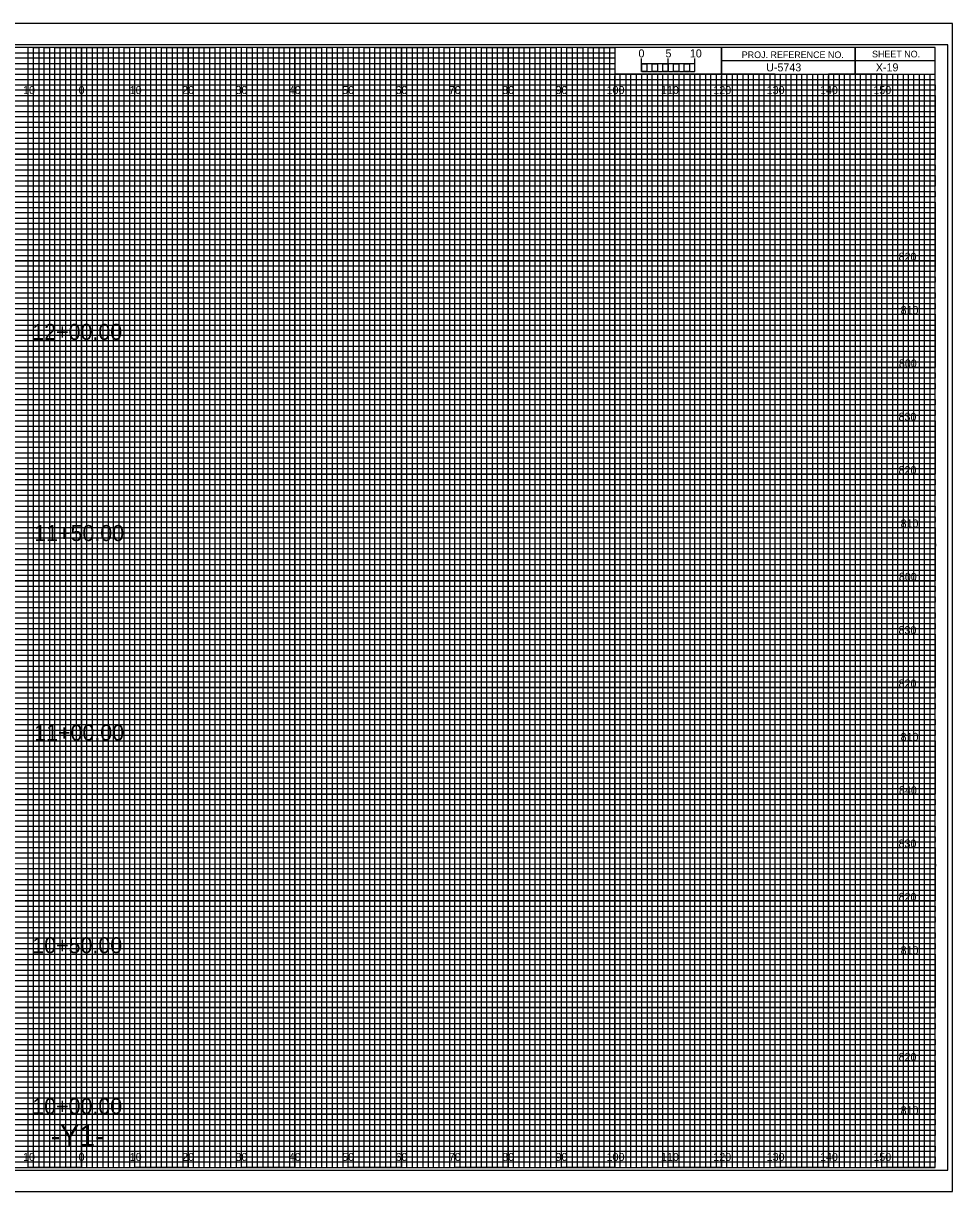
# Model space of a CAD drawing. Extents: x -13 to 323, y -4 to 214.
# Drawn here: x 149.1 to 323.3, y -4.5 to 214.5 of the extents above; entities that cross this region are included whole.
import ezdxf

# ---------------------------------------------------------------- set-up
doc = ezdxf.new("R2010")
doc.units = 0
for name, color, linetype in [('Exist Cross Section Cell', 7, 'Continuous'), ('Exist XS Center Line Elevation Label', 7, 'Continuous'), ('Exist XS Ground Line', 7, 'Continuous'), ('Old_Level_10', 7, 'Continuous'), ('Prop CMT Guardrail Graphics', 7, 'Continuous'), ('Prop CMT Pvmt Course 1', 7, 'Continuous'), ('Prop CMT Pvmt Course 2', 7, 'Continuous'), ('Prop CMT Pvmt Course 3', 7, 'Continuous'), ('Prop CMT Pvmt Surface', 7, 'Continuous'), ('Prop CMT Pvmt Surface Shoulder', 7, 'Continuous'), ('Prop CMT Shld Paved Course 1', 7, 'Continuous'), ('Prop CMT Shld Paved Course 2', 7, 'Continuous'), ('Prop CMT Shld Paved Course 3', 7, 'Continuous'), ('Prop CMT Slope Grass', 7, 'Continuous'), ('Prop CMT Subgrade Earthwork', 7, 'Continuous'), ('Prop XS Side Slope Text', 7, 'Continuous'), ('Scratch_Level_7', 7, 'Continuous')]:
    doc.layers.add(name, color=color, linetype=linetype)

msp = doc.modelspace()

# ---------------------------------------------------------------- linework, layer by layer
at = {"layer": 'Exist XS Center Line Elevation Label'}
for points in [[(145, 0), (155, 0), (155, 210), (165, 210), (165, 0), (175, 0), (175, 210), (185, 210), (185, 0), (195, 0), (195, 210), (205, 210), (205, 0), (215, 0), (215, 210), (225, 210), (225, 0), (235, 0), (235, 210), (245, 210), (245, 0), (255, 0), (255, 210), (259.93, 210), (260, 210), (260, 205), (264.99, 205), (264.99, 0), (275, 0), (275, 205), (285, 205), (285, 0), (295, 0), (295, 205), (305, 205), (305, 0), (315, 0), (315, 205)], [(0, 205), (275, 205)], [(0, 185), (320, 185), (320, 195), (0, 195)], [(0, 165), (320, 165), (320, 175), (0, 175)], [(0, 145), (320, 145), (320, 155), (0, 155)], [(0, 125), (320, 125), (320, 135), (0, 135)], [(0, 105), (320, 105), (320, 115), (0, 115)], [(0, 85), (320, 85), (320, 95), (0, 95)], [(0, 65), (320, 65), (320, 75), (0, 75)], [(0, 45), (320, 45), (320, 55), (0, 55)], [(0, 25), (320, 25), (320, 35), (0, 35)], [(0, 5), (320, 5), (320, 15), (0, 15)]]:
    msp.add_lwpolyline(points, dxfattribs=at)
at = {"layer": 'Exist XS Ground Line'}
for p, q in [((150, 210), (140, 210)), ((150, 0), (150, 210)), ((170, 210), (160, 210)), ((160, 210), (160, 0)), ((170, 0), (170, 210)), ((190, 210), (180, 210)), ((180, 210), (180, 0)), ((190, 0), (190, 210)), ((210, 210), (200, 210)), ((200, 210), (200, 0)), ((210, 0), (210, 210)), ((230, 210), (220, 210)), ((220, 210), (220, 0)), ((230, 0), (230, 210)), ((250, 210), (240, 210)), ((240, 210), (240, 0)), ((250, 0), (250, 210)), ((260, 210), (260, 0)), ((270, 0), (270, 205)), ((290, 205), (280, 205)), ((280, 205), (280, 0)), ((290, 0), (290, 205)), ((310, 205), (300, 205)), ((300, 205), (300, 0)), ((310, 0), (310, 205)), ((160, 0), (150, 0)), ((180, 0), (170, 0)), ((200, 0), (190, 0)), ((220, 0), (210, 0)), ((240, 0), (230, 0)), ((260, 0), (250, 0)), ((280, 0), (270, 0)), ((300, 0), (290, 0)), ((320, 0), (310, 0)), ((320, 0), (320, 0))]:
    msp.add_line(p, q, dxfattribs=at)
for points in [[(0, 200), (320, 200), (320, 190), (0, 190)], [(0, 180), (320, 180), (320, 170), (0, 170)], [(0, 160), (320, 160), (320, 150), (0, 150)], [(0, 140), (320, 140), (320, 130), (0, 130)], [(0, 120), (320, 120), (320, 110), (0, 110)], [(0, 100), (320, 100), (320, 90), (0, 90)], [(0, 80), (320, 80), (320, 70), (0, 70)], [(0, 60), (320, 60), (320, 50), (0, 50)], [(0, 40), (320, 40), (320, 30), (0, 30)], [(0, 20), (320, 20), (320, 10), (0, 10)]]:
    msp.add_lwpolyline(points, dxfattribs=at)
at = {"layer": 'Old_Level_10'}
for p, q in [((0, 209), (260, 209)), ((260, 209), (260, 207.98)), ((260, 207.98), (0, 207.98)), ((0, 207), (260, 207)), ((260, 205.89), (0, 205.89)), ((260, 207), (260, 205.89)), ((0, 204), (320, 204))]:
    msp.add_line(p, q, dxfattribs=at)
for points in [[(0, 203), (270, 203), (320, 203), (320, 202), (0, 202)], [(0, 201), (320, 201), (320, 199), (0, 199)], [(0, 198), (320, 198), (320, 197), (0, 196.98)], [(0, 196), (320, 196), (320, 194), (0, 194)], [(0, 193), (320, 193), (320, 192), (0, 192)], [(0, 191), (320, 191), (320, 189), (0, 189)], [(0, 188), (320, 188), (320, 187), (0, 187)], [(0, 186), (320, 186), (320, 184), (0, 184)], [(0, 183), (320, 183), (320, 182), (0, 182)], [(0, 181), (320, 181), (320, 179), (0, 179)], [(0, 178), (320, 178), (320, 177), (0, 177)], [(0, 176), (320, 176), (320, 173.95), (320, 173), (320, 172), (0, 172)], [(0, 174), (320, 174), (320, 173), (0, 173)], [(0, 171), (320, 171), (320, 169), (0, 169.03)], [(0, 169.03), (320, 169), (320, 168), (0, 168)], [(0, 167), (320, 167), (320, 166), (0, 166)], [(0, 164), (320, 164), (320, 163), (0, 163)], [(0, 162), (320, 162), (320, 161), (0, 161)], [(-0.07, 158.89), (320, 158.89), (320, 157.88), (-0.07, 157.88)], [(0, 157), (320, 157), (320, 156), (0, 156)], [(0, 154), (320, 154), (320, 153), (0, 153)], [(0, 152), (320, 152), (320, 151), (0, 151)], [(0, 149), (320, 149), (320, 148), (0, 148)], [(0, 147), (320, 147), (320, 146), (0, 146)], [(0, 144), (320, 144), (320, 143), (0, 143)], [(0, 142), (320, 142), (320, 141), (0, 141)], [(0, 139), (320, 139), (319.99, 137.98), (0, 138)], [(0, 137), (320, 137), (320, 136), (0, 136)], [(0, 134), (320, 134), (320, 133), (0, 133)], [(0, 132), (320, 132), (320, 131), (0, 131)], [(0, 129), (320, 129), (320, 128), (0, 128)], [(0, 127), (320, 127), (320, 126), (0, 126)], [(0, 124), (320, 124), (320, 123), (0, 123)], [(0, 122), (320, 122), (320, 121), (0, 121)], [(0, 119), (320, 119), (320, 118), (0, 118)], [(0, 116.99), (320.07, 116.91), (320, 116), (0, 116)], [(0, 114), (320, 114), (320, 113), (0, 113)], [(0, 112), (320, 112), (320, 111), (0, 111)], [(0, 109), (320, 109), (320, 108), (0, 108)], [(0, 107), (320, 107), (320, 106), (0, 106)], [(0, 104), (320, 104), (320, 103), (0, 103)], [(0, 102), (320, 102), (320, 101), (0, 101)], [(0, 99), (320, 99), (320, 98), (0, 98)], [(0, 97), (320, 97), (320, 96), (0, 96)], [(0, 94), (320, 94), (320, 93), (0, 93)], [(0, 92), (320, 92), (320, 91), (0, 91)], [(0, 89), (320, 89), (320, 88), (0, 88)], [(0, 87), (320, 87), (320, 86), (0, 86)], [(0, 84), (320, 84), (320, 83), (0, 83)], [(0, 82), (320, 82), (320, 81), (0, 81)], [(0, 79), (320, 79), (319.99, 77.98), (0, 78)], [(0, 77), (320, 77), (320, 76), (0, 76)], [(0, 74), (320, 74), (320, 73), (0, 73)], [(0, 72), (320, 72), (320, 71), (0, 71)], [(0, 69), (320, 69), (320, 68), (0, 68)], [(0, 67), (320, 67), (320, 66), (0, 66)], [(0, 64), (320, 64), (320, 63), (0, 63)], [(0, 62), (320, 62), (320, 61), (0, 61)], [(0, 59), (320, 59), (320, 58), (0, 58)], [(0, 56.99), (320.07, 56.91), (320, 56), (0, 56)], [(0, 54), (320, 54), (320, 53), (0, 53)], [(0, 52), (320, 52), (320, 51), (0, 51)], [(0, 49), (320, 49), (320, 48), (0, 48)], [(0, 47), (320, 47), (320, 46), (0, 46)], [(0, 44), (320, 44), (320, 43), (0, 43)], [(0, 42), (320, 42), (320, 41), (0, 41)], [(0, 39), (320, 39), (320, 38), (0, 38)], [(0, 37), (320, 37), (320, 36), (0, 36)], [(0, 34), (320, 34), (320, 33), (0, 33)], [(0, 32), (320, 32), (320, 31), (0, 31)], [(0, 29), (320, 29), (320, 28), (0, 28)], [(0, 27), (320, 27), (320, 26), (0, 26)], [(0, 24), (320, 24), (320, 23), (0, 23)], [(0, 22), (320, 22), (320, 21), (0, 21)], [(0, 19), (320, 19), (320, 18), (0, 18)], [(0, 17), (320, 17), (320, 16), (0, 16)], [(0, 14), (320, 14), (320, 13), (0, 13)], [(0, 12), (320, 12), (320, 11), (0, 11)], [(0, 9), (320, 9), (320, 8), (0, 8)], [(0, 7), (320, 7), (320, 6), (0, 6)], [(0, 4), (320, 4), (320, 3), (0, 3)], [(0, 2), (320, 2), (320, 1), (0, 1)]]:
    msp.add_lwpolyline(points, dxfattribs=at)
at = {"layer": 'Prop CMT Pvmt Course 2'}
msp.add_lwpolyline([(-10.8, -0.5), (322.4, -0.5), (322.4, 210.5), (-10.8, 210.5)], close=True, dxfattribs=at)
at = {"layer": 'Prop CMT Pvmt Course 3'}
for p, q in [((150, 0), (150, 210)), ((160, 0), (160, 210)), ((170, 0), (170, 210)), ((180, 0), (180, 210)), ((190, 0), (190, 210)), ((200, 0), (200, 210)), ((210, 0), (210, 210)), ((220, 0), (220, 210)), ((230, 0), (230, 210)), ((240, 0), (240, 210)), ((250, 0), (250, 210)), ((260, 0), (260, 204.69)), ((270, 0), (270, 204.69)), ((280, 0), (280, 204.69)), ((290, 0), (290, 204.69)), ((300, 0), (300, 204.69)), ((310, 0), (310, 204.69)), ((0, 200), (320, 200)), ((0, 190), (320, 190)), ((0, 180), (320, 180)), ((0, 170), (320, 170)), ((0, 160), (320, 160)), ((0, 150), (320, 150)), ((0, 140), (320, 140)), ((0, 130), (320, 130)), ((0, 120), (320, 120)), ((0, 110), (320, 110)), ((0, 100), (320, 100)), ((0, 90), (320, 90)), ((0, 80), (320, 80)), ((0, 70), (320, 70)), ((0, 60), (320, 60)), ((0, 50), (320, 50)), ((0, 40), (320, 40)), ((0, 30), (320, 30)), ((0, 20), (320, 20)), ((0, 10), (320, 10))]:
    msp.add_line(p, q, dxfattribs=at)
at = {"layer": 'Prop CMT Shld Paved Course 1'}
for p, q in [((305, 210), (305, 205)), ((305, 205), (305, 210)), ((280, 207.5), (280, 205)), ((320, 207.49), (280, 207.49)), ((280, 205), (320, 205))]:
    msp.add_line(p, q, dxfattribs=at)
for points in [[(320, 210), (0, 210), (0, 0), (320, 0)], [(280, 210), (260, 210), (260, 205.03), (280, 205.03)], [(320, 210), (280, 210), (280, 205), (320, 205)]]:
    msp.add_lwpolyline(points, close=True, dxfattribs=at)
at = {"layer": 'Prop CMT Shld Paved Course 2'}
for p, q in [((265, 205.49), (265, 207.9)), ((265, 206.9), (265, 207.9)), ((270, 205.49), (270, 207.9)), ((275, 205.49), (275, 207.9)), ((275, 206.9), (275, 207.9))]:
    msp.add_line(p, q, dxfattribs=at)
for points in [[(275, 206.9), (265, 206.9), (265, 205.49), (275, 205.49)], [(265, 206.9), (266, 206.9), (266, 205.49), (265, 205.49)], [(267, 206.9), (268, 206.9), (268, 205.49), (267, 205.49)], [(269, 206.9), (270, 206.9), (270, 205.49), (269, 205.49)], [(271, 206.9), (272, 206.9), (272, 205.49), (271, 205.49)], [(273, 206.9), (274, 206.9), (274, 205.49), (273, 205.49)]]:
    msp.add_lwpolyline(points, close=True, dxfattribs=at)
at = {"layer": 'Prop CMT Shld Paved Course 3'}
msp.add_lwpolyline([(-13.4, -4.5), (323.3, -4.5), (323.3, 214.5), (-13.4, 214.5)], close=True, dxfattribs=at)
at = {"layer": 'Prop CMT Subgrade Earthwork'}
for p, q in [((323.3, 214.5), (-13.4, 214.5)), ((-13.4, -4.5), (323.3, -4.5))]:
    msp.add_line(p, q, dxfattribs=at)
at = {"layer": 'Scratch_Level_7'}
for p, q in [((267, 205), (266.01, 205)), ((266.01, 205), (266.01, 0)), ((267, 0), (267, 205)), ((269, 205), (268, 205)), ((268, 205), (268, 0)), ((269, 0), (269, 205)), ((266.01, 0), (265, 0)), ((268, 0), (267, 0))]:
    msp.add_line(p, q, dxfattribs=at)
for points in [[(150, 0), (151, 0), (151, 210), (152, 210), (152, 0)], [(152, 0), (153, 0), (153, 210), (154, 210), (154, 0)], [(155, 0), (156, 0), (156, 210), (157, 210), (157, 0)], [(157, 0), (158, 0), (158, 210), (159, 210), (159, 0)], [(160, 0), (161, 0), (161, 210), (162, 210), (162, 0)], [(162, 0), (163, 0), (163, 210), (164, 210), (164, 0)], [(165, 0), (166, 0), (166, 210), (167, 210), (167, 0)], [(167, 0), (168, 0), (168, 210), (169, 210), (169, 0)], [(170, 0), (171, 0), (171, 210), (172, 210), (172, 0)], [(172, 0), (173, 0), (173, 210), (174, 210), (174, 0)], [(175, 0), (176, 0), (176, 210), (177, 210), (177, 0)], [(177, 0), (178, 0), (178, 210), (179, 210), (179, 0)], [(180, 0), (181, 0), (181, 210), (182, 210), (182, 0)], [(182, 0), (183, 0), (183, 210), (184, 210), (184, 0)], [(185, 0), (186, 0), (186, 210), (187, 210), (187, 0)], [(187, 0), (188, 0), (188, 210), (189, 210), (189, 0)], [(190, 0), (191, 0), (191, 210), (192, 210), (192, 0)], [(192, 0), (193, 0), (193, 210), (194, 210), (194, 0)], [(195, 0), (196, 0), (196, 210), (197, 210), (197, 0)], [(197, 0), (198, 0), (198, 210), (199, 210), (199, 0)], [(200, 0), (201, 0), (201, 210), (202, 210), (202, 0)], [(202, 0), (203, 0), (203, 210), (204, 210), (204, 0)], [(205, 0), (206, 0), (206, 210), (207, 210), (207, 0)], [(207, 0), (208, 0), (208, 210), (209, 210), (209, 0)], [(210, 0), (211, 0), (211, 210), (212, 210), (212, 0)], [(212, 0), (213, 0), (213, 210), (214, 210), (214, 0)], [(215, 0), (216, 0), (216, 210), (217, 210), (217, 0)], [(217, 0), (218, 0), (218, 210), (219, 210), (219, 0)], [(220, 0), (221, 0), (221, 210), (222, 210), (222, 0)], [(222, 0), (223, 0), (223, 210), (224, 210), (224, 0)], [(225, 0), (226, 0), (226, 210), (227, 210), (227, 0)], [(227, 0), (228, 0), (228, 210), (229, 210), (229, 0)], [(230, 0), (231, 0), (231, 210), (232, 210), (232, 0)], [(232, 0), (233, 0), (233, 210), (234, 210), (234, 0)], [(235, 0), (236, 0), (236, 210), (237, 210), (237, 0)], [(237, 0), (238, 0), (238, 210), (239, 210), (239, 0)], [(240, 0), (241, 0), (241, 210), (242, 210), (242, 0)], [(242, 0), (243, 0), (243, 210), (244, 210), (244, 0)], [(245, 0), (246, 0), (246, 210), (247, 210), (247, 0)], [(247, 0), (248, 0), (248, 210), (249, 210), (249, 0)], [(250, 0), (251, 0), (251, 210), (252, 210), (252, 0)], [(252, 0), (253, 0), (253, 210), (254, 210), (254, 0)], [(255, 0), (256, 0), (256, 210), (257, 210), (257, 0)], [(257, 0), (258, 0), (258, 210), (259, 210), (259, 0)], [(260, 0), (261, 0), (261, 205), (262.02, 205), (262.02, 0)], [(262, 0), (263, 0), (263, 205), (263.99, 205), (263.99, 0)], [(270, 0), (270.98, 0), (270.98, 205), (272, 205), (272, 0)], [(272, 0), (273, 0), (273, 205), (274.05, 205), (274.05, 0)], [(275, 0), (276, 0), (276, 205), (277, 205), (277, 0)], [(277, 0), (278, 0), (278, 205), (279, 205), (279, 0)], [(280, 0), (281, 0), (281, 205), (282, 205), (282, 0)], [(282, 0), (283, 0), (283, 205), (284, 205), (284, 0)], [(285, 0), (286, 0), (286, 205), (287, 205), (287, 0)], [(287, 0), (288, 0), (288, 205), (289, 205), (289, 0)], [(290, 0), (291, 0), (291, 205), (292, 205), (292, 0)], [(292, 0), (293, 0), (293, 205), (294, 205), (294, 0)], [(295, 0), (296, 0), (296, 205), (297, 205), (297, 0)], [(297, 0), (298, 0), (298, 205), (299, 205), (299, 0)], [(300, 0), (301, 0), (301, 205), (302, 205), (302, 0)], [(302, 0), (303, 0), (303, 205), (304, 205), (304, 0)], [(305, 0), (306, 0), (306, 205), (307, 205), (307, 0)], [(307, 0), (308, 0), (308, 205), (309, 205), (309, 0)], [(310, 0), (311, 0), (311, 205), (312, 205), (312, 0)], [(312, 0), (313, 0), (313, 205), (314, 205), (314, 0)], [(315, 0), (316, 0), (316, 205), (317, 205), (317, 0)], [(317, 0), (318, 0), (318, 205), (319, 205), (319, 0)]]:
    msp.add_lwpolyline(points, dxfattribs=at)

# ---------------------------------------------------------------- texts
at = {"layer": 'Exist Cross Section Cell'}
for s, p in [('10', (149.04, 201.25)), ('0', (159.45, 201.25)), ('0', (159.45, 201.25)), ('10', (169.04, 201.25)), ('20', (178.86, 201.25)), ('30', (188.86, 201.25)), ('40', (198.86, 201.25)), ('50', (208.86, 201.25)), ('60', (218.86, 201.25)), ('70', (228.86, 201.25)), ('80', (238.86, 201.25)), ('90', (248.86, 201.25)), ('100', (258.44, 201.25)), ('110', (268.62, 201.25)), ('120', (278.44, 201.25)), ('130', (288.44, 201.25)), ('140', (298.44, 201.25)), ('150', (308.44, 201.25)), ('10', (149.04, 1.25)), ('0', (159.45, 1.25)), ('0', (159.45, 1.25)), ('10', (169.04, 1.25)), ('20', (178.86, 1.25)), ('30', (188.86, 1.25)), ('40', (198.86, 1.25)), ('50', (208.86, 1.25)), ('60', (218.86, 1.25)), ('70', (228.86, 1.25)), ('80', (238.86, 1.25)), ('90', (248.86, 1.25)), ('100', (258.44, 1.25)), ('110', (268.62, 1.25)), ('120', (278.44, 1.25)), ('130', (288.44, 1.25)), ('140', (298.44, 1.25)), ('150', (308.44, 1.25))]:
    msp.add_text(s, height=1.5, dxfattribs=at).set_placement(p)
at = {"layer": 'Prop CMT Guardrail Graphics'}
msp.add_text('-Y1-', height=4, dxfattribs=at).set_placement((154.21, 4))
at = {"layer": 'Prop CMT Pvmt Course 1'}
msp.add_text('X-19', height=1.5, dxfattribs=at).set_placement((308.9, 205.5))
at = {"layer": 'Prop CMT Pvmt Surface'}
for s, p in [('820', (313.17, 170)), ('810', (313.55, 160)), ('800', (313.22, 150)), ('830', (313.16, 140)), ('820', (313.17, 130)), ('810', (313.55, 120)), ('800', (313.22, 110)), ('830', (313.16, 100)), ('820', (313.17, 90)), ('810', (313.55, 80)), ('840', (313.24, 70)), ('830', (313.16, 60)), ('820', (313.17, 50)), ('810', (313.55, 40)), ('820', (313.17, 20)), ('810', (313.55, 10))]:
    msp.add_text(s, height=1.5, dxfattribs=at).set_placement(p)
at = {"layer": 'Prop CMT Pvmt Surface Shoulder'}
for s, p in [('12+00.00', (150.77, 155.17)), ('11+50.00', (151.13, 117.46)), ('11+00.00', (151.13, 80.05)), ('10+50.00', (150.77, 40.19)), ('10+00.00', (150.77, 10.03))]:
    msp.add_text(s, height=3, dxfattribs=at).set_placement(p)
at = {"layer": 'Prop CMT Shld Paved Course 1'}
for s, p in [('PROJ. REFERENCE NO.', (283.77, 207.99)), ('SHEET NO.', (308.19, 208.12))]:
    msp.add_text(s, height=1.25, dxfattribs=at).set_placement(p)
at = {"layer": 'Prop CMT Shld Paved Course 2'}
msp.add_text('0', height=1.5, dxfattribs=at).set_placement((264.41, 208.12))
at = {"layer": 'Prop CMT Slope Grass'}
msp.add_text('U-5743', height=1.5, dxfattribs=at).set_placement((288.34, 205.5))
at = {"layer": 'Prop XS Side Slope Text'}
for s, p in [('5', (269.47, 208.12)), ('10', (274.04, 208.12))]:
    msp.add_text(s, height=1.5, dxfattribs=at).set_placement(p)

doc.saveas('drawing.dxf')
